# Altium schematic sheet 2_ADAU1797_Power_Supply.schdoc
size 601 x 429 mm; Symbol: Drawing-Symbol_A4; Device: Drawing-Symbol_A4; @Project Name: Slowpoke; @Page Count: 7; @Update Date: 2025-12-15; @Create Date: 2025-12-13; @Schematic Name: Slowpoke_Sch; @Page No: 2; @Page Name: ADAU1797_Power_Supply; Company: Analog Devices, Inc.; Version: V1.0; Page Size: A2; @Create Time: 14:28:29; @Update Time: 15:43:00; Width: 2338; Height: 1652; Region Start: 1; X Region Count: 6; Y Region Count: 4; Blade Width: 10; Title Block Position: 3; @Board Name: Slowpoke
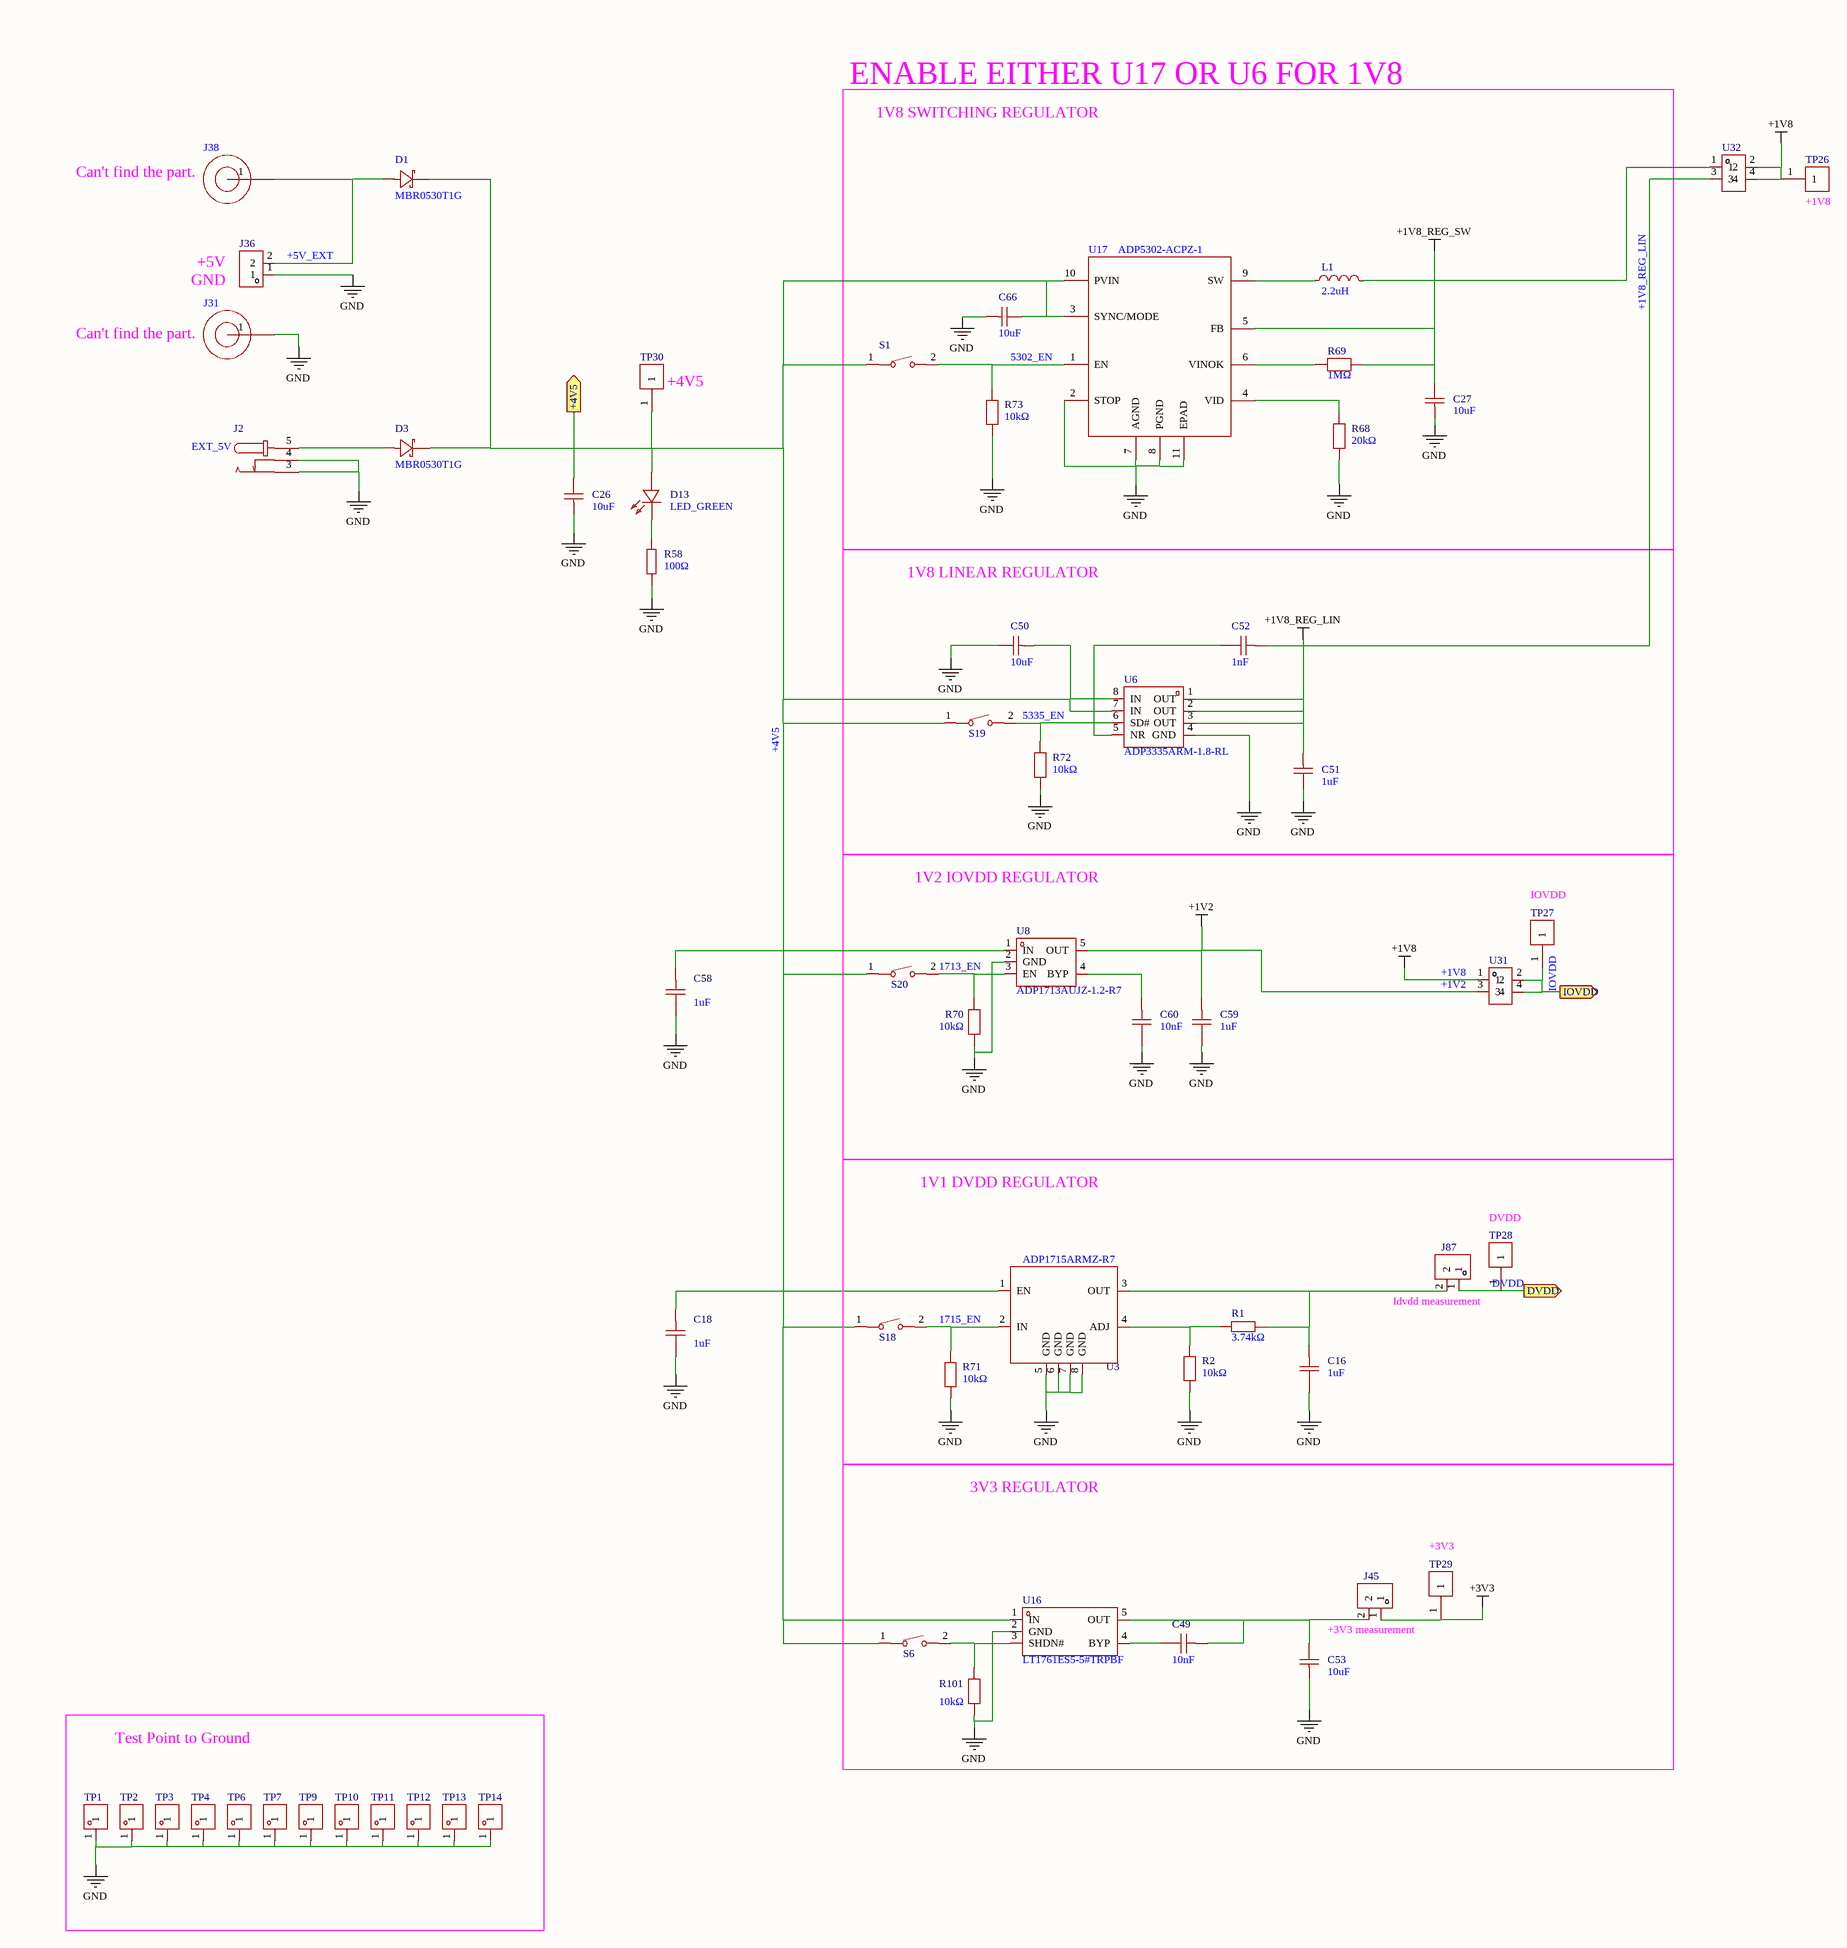
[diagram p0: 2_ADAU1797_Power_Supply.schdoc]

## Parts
C16  1uF  [C0402]
C18  1uF  [C0603]
C26  10uF  [C0805]
C27  10uF  [C0805]
C49  10nF  [C0402]
C50  10uF  [C0805]
C51  1uF  [C0402]
C52  1nF  [C0402]
C53  10uF  [C0805]
C58  1uF  [C0603]
C59  1uF  [C0402]
C60  10nF  [C0402]
C66  10uF  [C0805]
D1  MBR0530T1G  [SOD-123_L2.8-W1.8-LS3.9-FD]
D3  MBR0530T1G  [SOD-123_L2.8-W1.8-LS3.9-FD]
D13  LED_GREEN  [LED1206-R-RD_GREEN]
J2  EXT_5V  [DC-IN-TH_DC-509-ARL200-H142]
J31  (no value)  [J587-ND]
J36  PZ254V-11-02P  [HDR-TH_2P-P2.54-V-M]  (value not drawn)
J38  (no value)  [J587-ND]
J45  PZ254V-11-02P  [HDR-TH_2P-P2.54-V-M]  (value not drawn)
J87  PZ254V-11-02P  [HDR-TH_2P-P2.54-V-M]  (value not drawn)
L1  2.2uH  [L1210]
R1  3.74kΩ  [R0402]
R2  10kΩ  [R0402]
R58  100Ω  [R0805]
R68  20kΩ  [R0402]
R69  1MΩ  [R0402]
R70  10kΩ  [R0402]
R71  10kΩ  [R0402]
R72  10kΩ  [R0402]
R73  10kΩ  [R0402]
R101  10kΩ  [R0402]
S1  CHS-01TA1  [SW-SMD_2P-L5.4-W2.5-LS5.6]  (value not drawn)
S6  CHS-01TA1  [SW-SMD_2P-L5.4-W2.5-LS5.6]  (value not drawn)
S18  CHS-01TA1  [SW-SMD_2P-L5.4-W2.5-LS5.6]  (value not drawn)
S19  CHS-01TA1  [SW-SMD_2P-L5.4-W2.5-LS5.6]  (value not drawn)
S20  CHS-01TA1  [SW-SMD_2P-L5.4-W2.5-LS5.6]  (value not drawn)
TP1  RH-5001  [TEST-TH_BD2.54-P1.4_BLACK]  (value not drawn)
TP2  RH-5001  [TEST-TH_BD2.54-P1.4_BLACK]  (value not drawn)
TP3  RH-5001  [TEST-TH_BD2.54-P1.4_BLACK]  (value not drawn)
TP4  RH-5001  [TEST-TH_BD2.54-P1.4_BLACK]  (value not drawn)
TP6  RH-5001  [TEST-TH_BD2.54-P1.4_BLACK]  (value not drawn)
TP7  RH-5001  [TEST-TH_BD2.54-P1.4_BLACK]  (value not drawn)
TP9  RH-5001  [TEST-TH_BD2.54-P1.4_BLACK]  (value not drawn)
TP10  RH-5001  [TEST-TH_BD2.54-P1.4_BLACK]  (value not drawn)
TP11  RH-5001  [TEST-TH_BD2.54-P1.4_BLACK]  (value not drawn)
TP12  RH-5001  [TEST-TH_BD2.54-P1.4_BLACK]  (value not drawn)
TP13  RH-5001  [TEST-TH_BD2.54-P1.4_BLACK]  (value not drawn)
TP14  RH-5001  [TEST-TH_BD2.54-P1.4_BLACK]  (value not drawn)
TP26  RH-5000  [TEST-TH_BD2.54-P1.4_RED]  (value not drawn)
TP27  RH-5000  [TEST-TH_BD2.54-P1.4_RED]  (value not drawn)
TP28  RH-5000  [TEST-TH_BD2.54-P1.4_RED]  (value not drawn)
TP29  RH-5000  [TEST-TH_BD2.54-P1.4_RED]  (value not drawn)
TP30  RH-5000  [TEST-TH_BD2.54-P1.4_RED]  (value not drawn)
U3  ADP1715ARMZ-R7  [MSOP-8_L3.0-W3.0-P0.65-LS4.9-BL]
U6  ADP3335ARM-1.8-RL  [MSOP-8_L3.0-W3.0-P0.65-LS4.9-BL]
U8  ADP1713AUJZ-1.2-R7  [TSOT-5_L2.9-W1.6-P0.95-LS2.8-BR]
U16  LT1761ES5-5#TRPBF  [TSOT-23-5_L2.9-W1.6-P0.95-LS2.8-BR]
U17  ADP5302-ACPZ-1  [LFCSP-10_L3.0-W3.0-P0.50-BL-EP-1]
U31  ZX-PZ2.54-2-2PZZ  [HDR-TH_4P-P2.54-V-M-R2-C2-S2.54]  (value not drawn)
U32  ZX-PZ2.54-2-2PZZ  [HDR-TH_4P-P2.54-V-M-R2-C2-S2.54]  (value not drawn)

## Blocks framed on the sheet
1V8 SWITCHING REGULATOR: C27 C66 L1 R68 R69 R73 S1 U17
1V8 LINEAR REGULATOR: C50-C52 R72 S19 U6
1V2 IOVDD REGULATOR: C59 C60 R70 S20 TP27 U8 U31
1V1 DVDD REGULATOR: C16 J87 R1 R2 R71 S18 TP28 U3
3V3 REGULATOR: C49 C53 J45 R101 S6 TP29 U16
Test Point to Ground: TP1-TP4 TP6 TP7 TP9-TP14

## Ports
+4V5 (out), DVDD (out), IOVDD (out)

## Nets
+1V2: C59.2 U8.5(OUT) U31.3
+1V8: TP26.1 U31.1 U32.2 U32.4
+1V8_REG_LIN: C51.1 C52.2 U6.1(OUT) U6.2(OUT) U6.3(OUT) U32.3
+1V8_REG_SW: C27.2 L1.2 R69.2 U17.5(FB) U32.1
+3V3: J45.1 TP29.1
GND: C16.1 C18.1 C26.1 C27.1 C50.2 C51.2 C53.1 C58.1 C59.1 C60.1 C66.1 J2.3 J2.4 J31.1 J36.1 R2.1 R58.1 R68.1 R70.1 R71.1 R72.1 R73.1 R101.1 TP1.1 TP2.1 TP3.1 TP4.1 TP6.1 TP7.1 TP9.1 TP10.1 TP11.1 TP12.1 TP13.1 TP14.1 U3.5(GND) U3.6(GND) U3.7(GND) U3.8(GND) U6.4(GND) U8.2(GND) U16.2(GND) U17.2(STOP) U17.7(AGND) U17.8(PGND) U17.11(EPAD)
1713_EN: R70.2 S20.2 U8.3(EN)
1715_EN: R71.2 S18.2 U3.2(IN)
5302_EN: R73.2 S1.2 U17.1(EN)
5335_EN: R72.2 S19.2 U6.6(SD#)
+4V5: C18.2 C26.2 C50.1 C58.2 C66.2 D1.2(K) D3.2(K) D13.1(A) S1.1 S6.1 S18.1 S19.1 S20.1 TP30.1 U3.1(EN) U6.7(IN) U6.8(IN) U8.1(IN) U16.1(IN) U17.3(SYNC/MODE) U17.10(PVIN) ; port +4V5
+5V_EXT: D1.1(A) J36.2 J38.1
DVDD: J87.1 TP28.1 ; port DVDD
IOVDD: TP27.1 U31.2 U31.4 ; port IOVDD
NetC16_2: C16.2 J87.2 R1.2 U3.3(OUT)
NetC49_1: C49.1 U16.4(BYP)
NetC49_2: C49.2 C53.2 J45.2 U16.5(OUT)
NetC52_1: C52.1 U6.5(NR)
NetC60_2: C60.2 U8.4(BYP)
NetD3_1: D3.1(A) J2.5
NetD13_2: D13.2(K) R58.2
NetL1_1: L1.1 U17.9(SW)
NetR1_1: R1.1 R2.2 U3.4(ADJ)
NetR68_2: R68.2 U17.4(VID)
NetR69_1: R69.1 U17.6(VINOK)
NetR101_2: R101.2 S6.2 U16.3(SHDN#)

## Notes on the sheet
- ENABLE EITHER U17 OR U6 FOR 1V8
- (near J38) Can't find the part.
- (near J36) +5V
- (near TP26) +1V8
- GND
- (near J31) Can't find the part.
- (near TP30) +4V5
- (near TP27) IOVDD
- DVDD
- (near J87) Idvdd measurement
- (near TP29) +3V3
- +3V3 measurement

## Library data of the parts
C16 C59 = GRM155R70J105KA12D: Manufacturer: muRata(村田); Add into BOM: yes; Tolerance: ±10%
C18 C58 = GRM188R71C105KA12D: Manufacturer: muRata(村田); Add into BOM: yes; Tolerance: ±10%
C26 C50 C66 = CL21A106KPFNNNE: Manufacturer: SAMSUNG(三星); Add into BOM: yes; Tolerance: ±10%; Voltage Rating: 10V; Temperature Coefficient: X5R
C27 C53 = CL21B106KPQNNNE: Manufacturer: SAMSUNG(三星); Add into BOM: yes; Tolerance: ±10%; Voltage Rating: 10V; Temperature Coefficient: X7R
C49 C60 = 0402B103K250NT: Manufacturer: FH(风华); Add into BOM: yes; Tolerance: ±10%
C51 = CC0402KRX7R5BB105_C115046: Manufacturer: YAGEO(国巨); Symbol: CL21A106KPFNNNE; Add into BOM: yes; Tolerance: ±10%; Voltage Rating: 6.3V; Temperature Coefficient: X7R
C52 = GRM1555C1H102JA01D: Manufacturer: muRata(村田); Add into BOM: yes; Tolerance: ±5%; Voltage Rating: 50V; Temperature Coefficient: C0G
D1 D3 = MBR0530T1G_C7436545: Manufacturer: FUXINSEMI(富芯森美); Add into BOM: yes; Diode Configuration: Independent; Voltage - Forward(Vf@If): 430mV@0.5A; Voltage - DC Reverse(Vr): 30V; Current - Rectified: 500mA; Operating Junction Temperature Range: -55℃~+125℃; Non-Repetitive Peak Forward Surge Current: 5.5A
D13 = XL-3216UGC: Manufacturer: XINGLIGHT(成兴光); Add into BOM: yes; Illumination Color: Emerald Green; Voltage - Forward(Vf): 3.4V; Power(Watts): 70mW; Forward Current: 20mA; Wavelength - Dominant: 516nm~525nm; Peak Wavelength: 534nm; Lens Color: Water Clear; Luminous Intensity: 900mcd; Viewing Angle: 120°
J2 = DC-509-ARL200-H142: Manufacturer: XUNPU(讯普); Add into BOM: yes; Connector Type: DC Power Jack; Inside Contact Diameter: 2mm; Outside Contact Diameter: 5.5mm; Current Rating: 5A; Voltage Rating (Max): 30V
J31 J38 = J587-ND: Add into BOM: yes
J36 J45 J87 = PZ254V-11-02P: Manufacturer: XFCN(兴飞); Add into BOM: yes; Pin Structure: 1x2P; Pitch: 2.54mm; Circluar Pins/Square Pins: Pin Header
L1 = LQH32PN2R2NN0L: Manufacturer: muRata(村田); Add into BOM: yes; Tolerance: ±30%; Saturation Current (Isat): 1.55A
R1 = 0402WGF3741TCE: Manufacturer: UNI-ROYAL(厚声); Add into BOM: yes; Tolerance: ±1%; Power(Watts): 62.5mW; Voltage-Supply(Max): 50V; Temperature Coefficient: ±100ppm/℃
R2 R70-R72 R101 = HP02WAF1002TCE: Manufacturer: UNI-ROYAL(厚声); Add into BOM: yes; Tolerance: ±1%; Power(Watts): 100mW; Voltage-Supply(Max): 50V; Temperature Coefficient: ±100ppm/℃
R58 = 0805W8F1002T5E: Manufacturer: UNI-ROYAL(厚声); Add into BOM: yes; Tolerance: ±1%; Power(Watts): 125mW; Voltage-Supply(Max): 150V; Temperature Coefficient: ±100ppm/℃
R68 R69 R73 = CR0402F1M00Q10Z: Manufacturer: EVER OHMS(天二科技); Add into BOM: yes; Tolerance: ±1%; Temperature Coefficient: ±100ppm/℃
S1 S6 S18-S20 = CHS-01TA1: Manufacturer: NIDEC(尼得科); Add into BOM: yes
TP1-TP4 TP6 TP7 TP9-TP14 = RH-5001: Manufacturer: 荣和; Add into BOM: yes; Connector Type: Pin type (through board); Plastic Color: Black; Board Space (Diameter φ/ Length x Width): 2.5mm
TP26-TP30 = RH-5000: Manufacturer: 荣和; Add into BOM: yes; Connector Type: Pin Type (Through-Board); Plastic Color: Red; Board Space (Diameter φ/ Length x Width): 2.5mm
U3 = ADP1715ARMZ-R7: Manufacturer: ADI(亚德诺); Add into BOM: yes; Output Type: Adjustable; Maximum Input Voltage: 5.5V; Output Voltage: 800mV~5V; Output Current: 500mA; Dropout Voltage: 400mV@(500mA); standby current: 100uA; Output Polarity: Positive electrode; Number of Outputs: 1
U6 = ADP3335ARM-1.8-RL: Manufacturer: ADI(亚德诺); Add into BOM: yes; Maximum Input Voltage: 12V; Output Voltage: 1.8V; MAX Output Current: 500mA; Dropout Voltage: 0.37V@(500mA); standby current: 110uA; Output Polarity: Positive electrode; Number of Outputs: 1
U8 = ADP1713AUJZ-1.2-R7: Manufacturer: ADI(亚德诺); Add into BOM: yes; Output Type: Fixed; Maximum Input Voltage: 5.5V; Output Voltage: 1.2V; Output Current: 300mA; Power Supply Rejection Ratio (PSRR): 72dB@(1kHz); Dropout Voltage: 230mV@(300mA); standby current: 70uA; Output Polarity: Positive electrode; Number of Outputs: 1
U16 = LT1761ES5-5#TRPBF: Manufacturer: ADI(亚德诺); Add into BOM: yes; Output Type: Fixed; Voltage - Supply: 20V; Output Voltage: 5V; Output Current: 100mA; Power Supply Rejection Ratio (PSRR): 65dB@(120Hz); Output Configuration: Positive electrode; Number of Outputs: 1
U17 = ADP5320: Add into BOM: yes
U31 U32 = ZX-PZ2.54-2-2PZZ: Manufacturer: Megastar(兆星); Add into BOM: yes; Pin Structure: 2x2P; Pitch: 2.54mm; Circluar Pins/Square Pins: Policy; Current Rating: 3A; Voltage Rating (Max): 1kV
